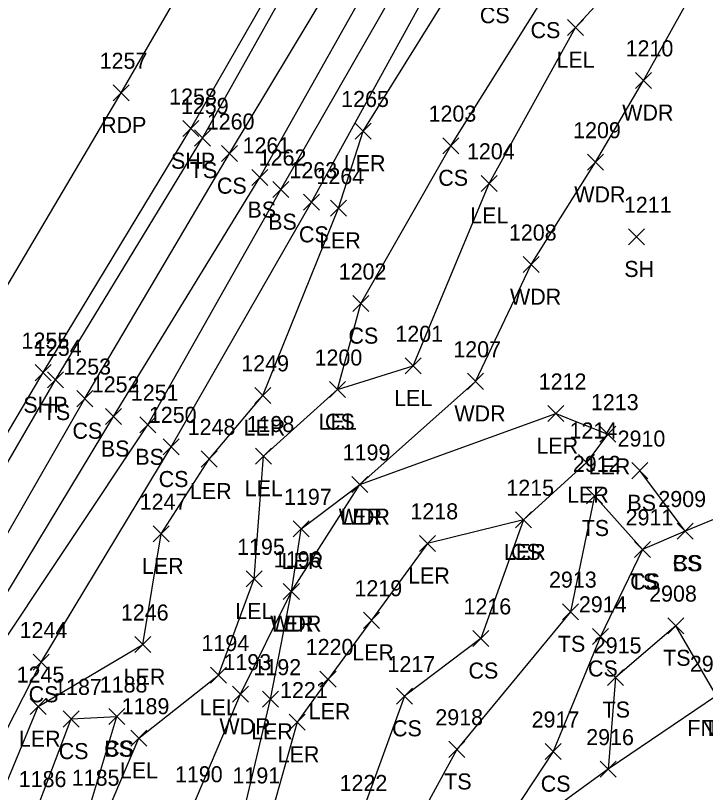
# Model space of a CAD drawing. Extents: x 1483143 to 1488182, y 802902 to 807581.
# Drawn here: x 1487266.4 to 1487352.5, y 805194.3 to 805291.1 of the extents above; entities that cross this region are included whole.
import ezdxf

# ---------------------------------------------------------------- set-up
doc = ezdxf.new("R2010")
doc.units = 0
for name, color, linetype in [('L_A', 7, 'Continuous'), ('L_I', 7, 'Continuous'), ('L_TIC', 7, 'Continuous'), ('LARO', 7, 'Continuous'), ('LAWA', 7, 'Continuous'), ('LELB', 7, 'Continuous'), ('LFNC', 7, 'Continuous'), ('P_A', 7, 'Continuous'), ('P_I', 7, 'Continuous'), ('P_TIC', 7, 'Continuous'), ('PET', 7, 'Continuous'), ('PSP', 7, 'Continuous')]:
    doc.layers.add(name, color=color, linetype=linetype)

msp = doc.modelspace()

# ---------------------------------------------------------------- linework, layer by layer
at = {"layer": 'L_TIC'}
for points in [[(1487335.292, 805288.621), (1487337.292, 805290.621)], [(1487337.292, 805288.621), (1487335.292, 805290.621)], [(1487343.765, 805282.023), (1487345.765, 805284.023)], [(1487345.765, 805282.023), (1487343.765, 805284.023)], [(1487288.786, 805274.848), (1487290.786, 805276.848)], [(1487290.786, 805274.848), (1487288.786, 805276.848)], [(1487308.811, 805275.714), (1487310.811, 805277.714)], [(1487310.811, 805275.714), (1487308.811, 805277.714)], [(1487319.742, 805273.887), (1487321.742, 805275.887)], [(1487321.742, 805273.887), (1487319.742, 805275.887)], [(1487292.132, 805272.903), (1487294.132, 805274.903)], [(1487294.132, 805272.903), (1487292.132, 805274.903)], [(1487337.784, 805271.819), (1487339.784, 805273.819)], [(1487339.784, 805271.819), (1487337.784, 805273.819)], [(1487295.939, 805269.919), (1487297.939, 805271.919)], [(1487297.939, 805269.919), (1487295.939, 805271.919)], [(1487324.532, 805269.193), (1487326.532, 805271.193)], [(1487326.532, 805269.193), (1487324.532, 805271.193)], [(1487298.524, 805268.417), (1487300.524, 805270.417)], [(1487300.524, 805268.417), (1487298.524, 805270.417)], [(1487302.36, 805266.837), (1487304.36, 805268.837)], [(1487304.36, 805266.837), (1487302.36, 805268.837)], [(1487305.73, 805266.094), (1487307.73, 805268.094)], [(1487307.73, 805266.094), (1487305.73, 805268.094)], [(1487342.893, 805262.523), (1487344.893, 805264.523)], [(1487344.893, 805262.523), (1487342.893, 805264.523)], [(1487329.766, 805259.066), (1487331.766, 805261.066)], [(1487331.766, 805259.066), (1487329.766, 805261.066)], [(1487308.537, 805254.209), (1487310.537, 805256.209)], [(1487310.537, 805254.209), (1487308.537, 805256.209)], [(1487315.034, 805246.442), (1487317.034, 805248.442)], [(1487317.034, 805246.442), (1487315.034, 805248.442)], [(1487270.44, 805244.688), (1487272.44, 805246.688)], [(1487272.44, 805244.688), (1487270.44, 805246.688)], [(1487322.828, 805244.512), (1487324.828, 805246.512)], [(1487324.828, 805244.512), (1487322.828, 805246.512)], [(1487305.606, 805243.481), (1487307.606, 805245.481)], [(1487307.606, 805243.481), (1487305.606, 805245.481)], [(1487305.606, 805243.481), (1487307.606, 805245.481)], [(1487307.606, 805243.481), (1487305.606, 805245.481)], [(1487274.109, 805242.356), (1487276.109, 805244.356)], [(1487276.109, 805242.356), (1487274.109, 805244.356)], [(1487296.309, 805242.756), (1487298.309, 805244.756)], [(1487298.309, 805242.756), (1487296.309, 805244.756)], [(1487277.653, 805240.134), (1487279.653, 805242.134)], [(1487279.653, 805240.134), (1487277.653, 805242.134)], [(1487332.841, 805240.493), (1487334.841, 805242.493)], [(1487334.841, 805240.493), (1487332.841, 805242.493)], [(1487281.957, 805239.106), (1487283.957, 805241.106)], [(1487283.957, 805239.106), (1487281.957, 805241.106)], [(1487339.348, 805237.916), (1487341.348, 805239.916)], [(1487341.348, 805237.916), (1487339.348, 805239.916)], [(1487284.862, 805236.335), (1487286.862, 805238.335)], [(1487286.862, 805236.335), (1487284.862, 805238.335)], [(1487296.396, 805235.192), (1487298.396, 805237.192)], [(1487298.396, 805235.192), (1487296.396, 805237.192)], [(1487289.621, 805234.832), (1487291.621, 805236.832)], [(1487291.621, 805234.832), (1487289.621, 805236.832)], [(1487336.67, 805234.385), (1487338.67, 805236.385)], [(1487338.67, 805234.385), (1487336.67, 805236.385)], [(1487343.332, 805233.379), (1487345.332, 805235.379)], [(1487345.332, 805233.379), (1487343.332, 805235.379)], [(1487308.392, 805231.65), (1487310.392, 805233.65)], [(1487310.392, 805231.65), (1487308.392, 805233.65)], [(1487308.392, 805231.65), (1487310.392, 805233.65)], [(1487310.392, 805231.65), (1487308.392, 805233.65)], [(1487337.662, 805230.229), (1487339.662, 805232.229)], [(1487339.662, 805230.229), (1487337.662, 805232.229)], [(1487328.8, 805227.251), (1487330.8, 805229.251)], [(1487330.8, 805227.251), (1487328.8, 805229.251)], [(1487328.8, 805227.251), (1487330.8, 805229.251)], [(1487330.8, 805227.251), (1487328.8, 805229.251)], [(1487283.628, 805225.504), (1487285.628, 805227.504)], [(1487285.628, 805225.504), (1487283.628, 805227.504)], [(1487301.061, 805226.116), (1487303.061, 805228.116)], [(1487303.061, 805226.116), (1487301.061, 805228.116)], [(1487348.982, 805225.845), (1487350.982, 805227.845)], [(1487350.982, 805225.845), (1487348.982, 805227.845)], [(1487348.982, 805225.845), (1487350.982, 805227.845)], [(1487350.982, 805225.845), (1487348.982, 805227.845)], [(1487316.835, 805224.311), (1487318.835, 805226.311)], [(1487318.835, 805224.311), (1487316.835, 805226.311)], [(1487343.674, 805223.559), (1487345.674, 805225.559)], [(1487345.674, 805223.559), (1487343.674, 805225.559)], [(1487343.674, 805223.559), (1487345.674, 805225.559)], [(1487345.674, 805223.559), (1487343.674, 805225.559)], [(1487295.215, 805219.881), (1487297.215, 805221.881)], [(1487297.215, 805219.881), (1487295.215, 805221.881)], [(1487299.853, 805218.322), (1487301.853, 805220.322)], [(1487301.853, 805218.322), (1487299.853, 805220.322)], [(1487299.853, 805218.322), (1487301.853, 805220.322)], [(1487301.853, 805218.322), (1487299.853, 805220.322)], [(1487334.69, 805215.793), (1487336.69, 805217.793)], [(1487336.69, 805215.793), (1487334.69, 805217.793)], [(1487309.864, 805214.723), (1487311.864, 805216.723)], [(1487311.864, 805214.723), (1487309.864, 805216.723)], [(1487347.823, 805214.051), (1487349.823, 805216.051)], [(1487349.823, 805214.051), (1487347.823, 805216.051)], [(1487323.508, 805212.456), (1487325.508, 805214.456)], [(1487325.508, 805212.456), (1487323.508, 805214.456)], [(1487338.418, 805212.719), (1487340.418, 805214.719)], [(1487340.418, 805212.719), (1487338.418, 805214.719)], [(1487281.34, 805211.696), (1487283.34, 805213.696)], [(1487283.34, 805211.696), (1487281.34, 805213.696)], [(1487268.648, 805209.502), (1487270.648, 805211.502)], [(1487270.648, 805209.502), (1487268.648, 805211.502)], [(1487290.772, 805207.886), (1487292.772, 805209.886)], [(1487292.772, 805207.886), (1487290.772, 805209.886)], [(1487304.427, 805207.398), (1487306.427, 805209.398)], [(1487306.427, 805207.398), (1487304.427, 805209.398)], [(1487340.271, 805207.596), (1487342.271, 805209.596)], [(1487342.271, 805207.596), (1487340.271, 805209.596)], [(1487293.517, 805205.511), (1487295.517, 805207.511)], [(1487295.517, 805205.511), (1487293.517, 805207.511)], [(1487313.972, 805205.26), (1487315.972, 805207.26)], [(1487315.972, 805205.26), (1487313.972, 805207.26)], [(1487297.253, 805204.883), (1487299.253, 805206.883)], [(1487299.253, 805204.883), (1487297.253, 805206.883)], [(1487268.282, 805203.963), (1487270.282, 805205.963)], [(1487270.282, 805203.963), (1487268.282, 805205.963)], [(1487272.394, 805202.421), (1487274.394, 805204.421)], [(1487274.394, 805202.421), (1487272.394, 805204.421)], [(1487278.078, 805202.721), (1487280.078, 805204.721)], [(1487280.078, 805202.721), (1487278.078, 805204.721)], [(1487278.078, 805202.721), (1487280.078, 805204.721)], [(1487280.078, 805202.721), (1487278.078, 805204.721)], [(1487300.571, 805202.024), (1487302.571, 805204.024)], [(1487302.571, 805202.024), (1487300.571, 805204.024)], [(1487280.822, 805200.015), (1487282.822, 805202.015)], [(1487282.822, 805200.015), (1487280.822, 805202.015)], [(1487320.51, 805198.638), (1487322.51, 805200.638)], [(1487322.51, 805198.638), (1487320.51, 805200.638)], [(1487332.52, 805198.357), (1487334.52, 805200.357)], [(1487334.52, 805198.357), (1487332.52, 805200.357)], [(1487339.385, 805196.167), (1487341.385, 805198.167)], [(1487341.385, 805196.167), (1487339.385, 805198.167)], [(1487339.385, 805196.167), (1487341.385, 805198.167)], [(1487341.385, 805196.167), (1487339.385, 805198.167)]]:
    msp.add_lwpolyline(points, dxfattribs=at)
at = {"layer": 'LARO'}
for points in [[(1487124.309, 804973.133), (1487145.495, 805006.811), (1487169.765, 805044.382), (1487180.591, 805057.867), (1487189.804, 805070.165), (1487199.3, 805080.956), (1487217.888, 805101.739), (1487229.452, 805124.322), (1487246.834, 805150.762), (1487254.408, 805169.191), (1487269.282, 805204.963), (1487282.34, 805212.696), (1487284.628, 805226.504), (1487290.621, 805235.832), (1487297.309, 805243.756), (1487306.73, 805267.094), (1487309.811, 805276.714), (1487327.694, 805305.395), (1487333.495, 805320.053), (1487351.266, 805341.809), (1487376.578, 805390.128), (1487400.895, 805431.242), (1487423.768, 805476.171), (1487448.724, 805522.614)], [(1487275.818, 805186.86), (1487281.822, 805201.015), (1487291.772, 805208.886), (1487296.215, 805220.881), (1487297.396, 805236.192), (1487306.606, 805244.481), (1487316.034, 805247.442), (1487325.532, 805270.193), (1487336.292, 805289.621), (1487349.275, 805303.757), (1487363.038, 805323.383), (1487373.749, 805338.949), (1487382.276, 805358.579), (1487388.761, 805365.445), (1487390.531, 805372.852), (1487405.186, 805401.025), (1487414.253, 805416.495), (1487427.797, 805437.512), (1487440.025, 805462.349), (1487458.802, 805482.343), (1487468.718, 805503.534)], [(1487283.613, 805140.295), (1487283.503, 805155.258), (1487287.651, 805171.019), (1487295.07, 805192.387), (1487298.253, 805205.883), (1487300.853, 805219.322), (1487302.061, 805227.116), (1487309.392, 805232.65), (1487333.841, 805241.493), (1487340.348, 805238.916), (1487337.67, 805235.385), (1487329.8, 805228.251), (1487317.835, 805225.311), (1487310.864, 805215.723), (1487305.427, 805208.398), (1487301.571, 805203.024), (1487297.08, 805187.058), (1487292.138, 805173.059), (1487289.577, 805160.654), (1487296.269, 805154.423), (1487288.878, 805150.065), (1487288.247, 805139.797)]]:
    msp.add_lwpolyline(points, dxfattribs=at)
at = {"layer": 'LAWA'}
msp.add_lwpolyline([(1487288.549, 805192.531), (1487294.517, 805206.511), (1487300.853, 805219.322), (1487309.392, 805232.65), (1487323.828, 805245.512), (1487330.766, 805260.066), (1487338.784, 805272.819), (1487344.765, 805283.023), (1487356.048, 805303.3), (1487368.202, 805318.297), (1487378.284, 805337.624), (1487391.65, 805357.447), (1487395.196, 805367.589), (1487402.103, 805377.948), (1487420.004, 805408.549), (1487434.601, 805433.131), (1487446.378, 805459.815), (1487458.802, 805482.343), (1487472.47, 805498.819)], dxfattribs=at)
at = {"layer": 'LELB'}
for points in [[(1487199.3, 805080.956), (1487209.02, 805107.055), (1487224.533, 805127.205), (1487240.955, 805152.244), (1487249.952, 805171.944), (1487269.648, 805210.502), (1487285.862, 805237.335), (1487303.36, 805267.837), (1487322.245, 805302.174), (1487347.449, 805347.065), (1487376.578, 805390.128), (1487398.579, 805433.784), (1487419.884, 805479.749), (1487445.409, 805524.092), (1487470.452, 805569.861), (1487486.06, 805603.157), (1487492.097, 805615.557), (1487500.681, 805632.415), (1487507.332, 805640.171), (1487520.295, 805671.343), (1487528.77, 805686.312), (1487539.175, 805698.489)], [(1487108.708, 804980.785), (1487132.659, 805016.317), (1487156.922, 805053.978), (1487173.308, 805079.976), (1487194.464, 805114.79), (1487207.052, 805135.954), (1487220.858, 805159.726), (1487233.381, 805181.298), (1487254.332, 805216.269), (1487271.44, 805245.688), (1487289.786, 805275.848), (1487308.885, 805309.935), (1487335.603, 805356.15), (1487359.272, 805398.593), (1487383.943, 805443.568), (1487406.655, 805485.41), (1487431.448, 805531.239)], [(1487141.454, 805012.57), (1487160.97, 805051.582), (1487177.593, 805077.874), (1487198.803, 805111.861), (1487211.591, 805133.505), (1487225.912, 805156.731), (1487238.62, 805176.26), (1487258.279, 805214.163), (1487275.109, 805243.356), (1487293.132, 805273.903), (1487313.265, 805307.347), (1487339.043, 805353.081), (1487362.827, 805397.005), (1487388.553, 805442.861), (1487410.035, 805483.235), (1487436.066, 805529.533)], [(1487115.553, 804977.3), (1487141.454, 805012.57), (1487163.511, 805049.719), (1487181.313, 805075.616), (1487202.214, 805110.172), (1487217.826, 805130.451), (1487232.003, 805156.359), (1487242.541, 805175.795), (1487260.943, 805211.878), (1487278.653, 805241.134), (1487296.939, 805270.919), (1487316.027, 805304.832), (1487341.87, 805350.704), (1487367.603, 805395.335), (1487392.627, 805437.945), (1487413.83, 805481.527), (1487440.22, 805526.888)], [(1487119.266, 804975.748), (1487145.32, 805010.107), (1487166.095, 805047.536), (1487184.558, 805073.643), (1487204.895, 805108.117), (1487221.472, 805128.3), (1487235.078, 805155.216), (1487247.476, 805170.55), (1487262.965, 805210.135), (1487282.957, 805240.106), (1487299.524, 805269.417), (1487319.055, 805303.467), (1487344.423, 805349.026), (1487372.123, 805390.856), (1487397.582, 805436.46), (1487417.004, 805480.798), (1487442.282, 805525.803)], [(1487306.606, 805244.481), (1487309.537, 805255.209), (1487320.742, 805274.887), (1487332.255, 805293.295), (1487346.726, 805329.479), (1487355.328, 805337.269), (1487367.561, 805346.194), (1487373.174, 805345.311), (1487376.363, 805375.932), (1487391.588, 805394.259), (1487397.321, 805413.81), (1487403.027, 805424.175), (1487412.589, 805429.383), (1487414.659, 805438.851), (1487433.831, 805470.604), (1487438.058, 805486.565), (1487449.506, 805502.694)], [(1487374.549, 805240.192), (1487374.605, 805242.267), (1487356.902, 805238.185), (1487355.834, 805229.258), (1487349.982, 805226.845), (1487344.332, 805234.379)], [(1487344.674, 805224.559), (1487338.662, 805231.229), (1487335.69, 805216.793), (1487321.51, 805199.638), (1487311.926, 805182.13), (1487306.809, 805166.693), (1487301.176, 805144.211)], [(1487329.8, 805228.251), (1487324.508, 805213.456), (1487314.972, 805206.26), (1487309.568, 805191.448), (1487302.21, 805175.354), (1487296.269, 805154.423)], [(1487349.982, 805226.845), (1487344.674, 805224.559), (1487339.418, 805213.719), (1487333.52, 805199.357), (1487324.399, 805185.566)], [(1487353.901, 805206.306), (1487348.823, 805215.051), (1487341.271, 805208.596), (1487340.385, 805197.167)], [(1487243.744, 805075.84), (1487236.873, 805078.959), (1487238.69, 805086.414), (1487239.993, 805090.196), (1487242.656, 805101.918), (1487242.453, 805110.69), (1487247.202, 805124.728), (1487252.074, 805141.927), (1487257.351, 805153.283), (1487261.024, 805166.684), (1487265.703, 805175.236), (1487270.248, 805187.46), (1487269.029, 805191.929), (1487273.394, 805203.421), (1487279.078, 805203.721)], [(1487270.248, 805187.46), (1487274.919, 805187.304), (1487275.591, 805192.096), (1487279.078, 805203.721)]]:
    msp.add_lwpolyline(points, dxfattribs=at)
at = {"layer": 'LFNC'}
msp.add_lwpolyline([(1487486.093, 805303.625), (1487464.014, 805287.372), (1487426.013, 805259.985), (1487401.416, 805242.523), (1487400.189, 805241.822), (1487381.812, 805228.112), (1487374.751, 805223.041), (1487372.522, 805220.639), (1487362.235, 805213.48), (1487358.334, 805209.86), (1487353.901, 805206.306), (1487340.385, 805197.167), (1487324.399, 805185.566), (1487312.705, 805164.898), (1487301.176, 805144.211), (1487298.042, 805137.825), (1487294.364, 805131.506), (1487284.562, 805115.259), (1487273.31, 805094.592), (1487256.779, 805068.371), (1487246.919, 805049.651), (1487232.592, 805026.135), (1487217.263, 805000.445), (1487203.238, 804976.049)], dxfattribs=at)
at = {"layer": 'P_TIC'}
for points in [[(1487278.635, 805280.477), (1487280.635, 805282.477)], [(1487280.635, 805280.477), (1487278.635, 805282.477)], [(1487287.304, 805276.017), (1487289.304, 805278.017)], [(1487289.304, 805276.017), (1487287.304, 805278.017)], [(1487268.889, 805245.596), (1487270.889, 805247.596)], [(1487270.889, 805245.596), (1487268.889, 805247.596)]]:
    msp.add_lwpolyline(points, dxfattribs=at)
at = {"layer": 'PET'}
msp.add_lwpolyline([(1487100.013, 804984.315), (1487124.371, 805022.555), (1487148.185, 805060.933), (1487163.616, 805085.689), (1487185.289, 805121.771), (1487197.783, 805142.122), (1487211.625, 805165.776), (1487224.008, 805186.828), (1487244.774, 805222.102), (1487262.9, 805253.279), (1487279.635, 805281.477), (1487299.464, 805315.66), (1487325.706, 805361.734), (1487348.035, 805401.833), (1487373.611, 805448.47), (1487396.331, 805490.411), (1487421.904, 805537.943)], dxfattribs=at)
at = {"layer": 'PSP'}
msp.add_lwpolyline([(1487105.23, 804982.128), (1487129.957, 805018.353), (1487154.678, 805055.529), (1487171.016, 805081.934), (1487192.507, 805116.631), (1487204.718, 805136.953), (1487219.028, 805160.876), (1487231.845, 805182.507), (1487252.473, 805217.194), (1487269.889, 805246.596), (1487288.304, 805277.017), (1487307.741, 805310.873), (1487334.082, 805357.489), (1487356.353, 805397.118), (1487382.378, 805444.502), (1487405.026, 805486.212), (1487429.801, 805532.421)], dxfattribs=at)

# ---------------------------------------------------------------- texts
at = {"layer": 'L_A'}
for s, p in [('CS', (1487324.371, 805290.157)), ('CS', (1487330.696, 805288.295)), ('LEL', (1487333.93, 805284.621)), ('WDR', (1487342.127, 805278.023)), ('LER', (1487307.394, 805271.714)), ('TS', (1487288.195, 805270.848)), ('CS', (1487319.183, 805269.887)), ('CS', (1487291.573, 805268.903)), ('WDR', (1487336.146, 805267.819)), ('BS', (1487295.38, 805265.919)), ('LEL', (1487323.169, 805265.193)), ('BS', (1487297.965, 805264.417)), ('CS', (1487301.801, 805262.837)), ('LER', (1487304.313, 805262.094)), ('SH', (1487342.381, 805258.523)), ('WDR', (1487328.128, 805255.066)), ('CS', (1487307.978, 805250.209)), ('LEL', (1487313.671, 805242.442)), ('TS', (1487269.85, 805240.688)), ('WDR', (1487321.19, 805240.512)), ('LEL', (1487304.244, 805239.481)), ('CS', (1487305.047, 805239.481)), ('CS', (1487273.55, 805238.356)), ('LER', (1487294.892, 805238.756)), ('BS', (1487277.094, 805236.134)), ('LER', (1487331.424, 805236.493)), ('BS', (1487281.398, 805235.106)), ('LER', (1487337.931, 805233.916)), ('CS', (1487284.303, 805232.335)), ('LER', (1487288.203, 805230.832)), ('LEL', (1487295.034, 805231.192)), ('LER', (1487335.253, 805230.385)), ('BS', (1487342.773, 805229.379)), ('WDR', (1487306.754, 805227.65)), ('LER', (1487306.974, 805227.65)), ('TS', (1487337.071, 805226.229)), ('LER', (1487327.382, 805223.251)), ('CS', (1487328.241, 805223.251)), ('LER', (1487299.644, 805222.116)), ('CS', (1487348.423, 805221.845)), ('BS', (1487348.423, 805221.845)), ('LER', (1487282.211, 805221.504)), ('LER', (1487315.418, 805220.311)), ('TS', (1487343.083, 805219.559)), ('CS', (1487343.115, 805219.559)), ('LEL', (1487293.853, 805215.881)), ('WDR', (1487298.215, 805214.322)), ('LER', (1487298.436, 805214.322)), ('TS', (1487334.099, 805211.793)), ('LER', (1487308.446, 805210.723)), ('TS', (1487347.232, 805210.051)), ('CS', (1487322.949, 805208.456)), ('CS', (1487337.859, 805208.719)), ('LER', (1487279.922, 805207.696)), ('CS', (1487268.089, 805205.502)), ('LEL', (1487289.409, 805203.886)), ('LER', (1487303.01, 805203.398)), ('TS', (1487339.68, 805203.596)), ('WDR', (1487291.88, 805201.511)), ('CS', (1487313.413, 805201.26)), ('FNWW', (1487350.248, 805201.306)), ('TS', (1487352.311, 805201.306)), ('LER', (1487295.836, 805200.883)), ('LER', (1487266.864, 805199.963)), ('CS', (1487271.835, 805198.421)), ('CS', (1487277.519, 805198.721)), ('BS', (1487277.519, 805198.721)), ('LER', (1487299.154, 805198.024)), ('LEL', (1487279.46, 805196.015)), ('TS', (1487319.919, 805194.638)), ('CS', (1487331.961, 805194.357))]:
    msp.add_text(s, height=2, dxfattribs=at).set_placement(p)
at = {"layer": 'L_I'}
for s, p in [('1210', (1487342.553, 805286.023)), ('1265', (1487307.071, 805279.714)), ('1259', (1487287.085, 805278.848)), ('1203', (1487317.97, 805277.887)), ('1260', (1487290.305, 805276.903)), ('1209', (1487336.005, 805275.819)), ('1261', (1487294.766, 805273.919)), ('1204', (1487322.76, 805273.193)), ('1262', (1487296.784, 805272.417)), ('1263', (1487300.62, 805270.837)), ('1264', (1487303.99, 805270.094)), ('1211', (1487342.334, 805266.523)), ('1208', (1487327.994, 805263.066)), ('1202', (1487306.765, 805258.209)), ('1201', (1487313.829, 805250.442)), ('1254', (1487268.747, 805248.688)), ('1207', (1487321.056, 805248.512)), ('1249', (1487294.608, 805246.756)), ('1200', (1487303.748, 805247.481)), ('1200', (1487303.748, 805247.481)), ('1253', (1487272.416, 805246.356)), ('1252', (1487275.96, 805244.134)), ('1212', (1487331.715, 805244.493)), ('1251', (1487280.832, 805243.106)), ('1213', (1487338.222, 805241.916)), ('1250', (1487283.083, 805240.335)), ('1198', (1487295.27, 805239.192)), ('1248', (1487287.928, 805238.832)), ('1214', (1487335.544, 805238.385)), ('2910', (1487341.552, 805237.379)), ('1199', (1487307.258, 805235.65)), ('1199', (1487307.258, 805235.65)), ('2912', (1487335.969, 805234.229)), ('1215', (1487327.674, 805231.251)), ('1215', (1487327.674, 805231.251)), ('1247', (1487281.936, 805229.504)), ('1197', (1487299.935, 805230.116)), ('2909', (1487346.636, 805229.845)), ('2909', (1487346.636, 805229.845)), ('1218', (1487315.709, 805228.311)), ('2911', (1487342.548, 805227.559)), ('2911', (1487342.548, 805227.559)), ('1195', (1487294.089, 805223.881)), ('1196', (1487298.672, 805222.322)), ('1196', (1487298.672, 805222.322)), ('2913', (1487332.997, 805219.793)), ('1219', (1487308.73, 805218.723)), ('2908', (1487345.484, 805218.051)), ('2914', (1487336.725, 805216.719)), ('1216', (1487322.326, 805216.456)), ('1246', (1487279.592, 805215.696)), ('1244', (1487266.955, 805213.502)), ('1194', (1487289.646, 805211.886)), ('1220', (1487302.648, 805211.398)), ('2915', (1487338.578, 805211.596)), ('1193', (1487292.391, 805209.511)), ('1217', (1487312.846, 805209.26)), ('2907', (1487350.563, 805209.306)), ('2907', (1487350.563, 805209.306)), ('1192', (1487296.127, 805208.883)), ('1245', (1487266.589, 805207.963)), ('1187', (1487271.268, 805206.421)), ('1188', (1487276.952, 805206.721)), ('1188', (1487276.952, 805206.721)), ('1221', (1487299.445, 805206.024)), ('1189', (1487279.689, 805204.015)), ('2918', (1487318.817, 805202.638)), ('2917', (1487330.827, 805202.357)), ('2916', (1487337.637, 805200.167)), ('2916', (1487337.637, 805200.167)), ('1190', (1487286.337, 805195.531)), ('1186', (1487266.848, 805194.929)), ('1186', (1487266.848, 805194.929)), ('1185', (1487273.465, 805195.096)), ('1185', (1487273.465, 805195.096)), ('1191', (1487293.511, 805195.387)), ('1222', (1487306.875, 805194.448))]:
    msp.add_text(s, height=2, dxfattribs=at).set_placement(p)
at = {"layer": 'P_A'}
for s, p in [('RDP', (1487277.123, 805276.477)), ('SHP', (1487285.839, 805272.017)), ('SHP', (1487267.424, 805241.596))]:
    msp.add_text(s, height=2, dxfattribs=at).set_placement(p)
at = {"layer": 'P_I'}
for s, p in [('1257', (1487276.942, 805284.477)), ('1258', (1487285.611, 805280.017)), ('1255', (1487267.196, 805249.596))]:
    msp.add_text(s, height=2, dxfattribs=at).set_placement(p)

doc.saveas('drawing.dxf')
